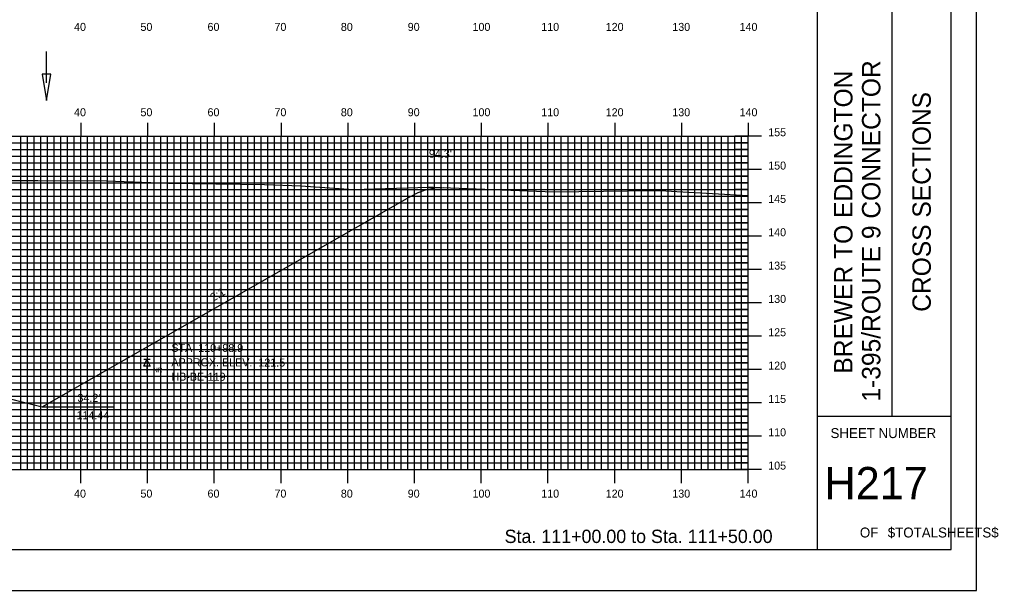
# Model space of a CAD drawing. Extents: x 1769661 to 1770005, y 442591 to 442811.
# Drawn here: x 1769857.8 to 1770004.5, y 442590.5 to 442676.2 of the extents above; entities that cross this region are included whole.
import ezdxf

# ---------------------------------------------------------------- set-up
doc = ezdxf.new("R2010")
doc.units = 0
for name, color, linetype in [('ANNOTATION', 7, 'Continuous'), ('BORDER', 7, 'Continuous'), ('BORING - NO REFUSAL', 7, 'Continuous'), ('D_Drainage_Ditch_Line', 7, 'Continuous'), ('D_Roadway_Centerline', 7, 'Continuous'), ('D_Roadway_SlopeLines', 7, 'Continuous'), ('D_Text_Standard', 7, 'Continuous'), ('H_V ANNOTATION', 7, 'Continuous'), ('MAJOR', 7, 'Continuous'), ('MINOR', 7, 'Continuous'), ('PDRAIN', 7, 'Continuous'), ('PLOT BOUNDARY', 7, 'Continuous'), ('S_Roadway_Centerline', 7, 'Continuous')]:
    doc.layers.add(name, color=color, linetype=linetype)

msp = doc.modelspace()

# ---------------------------------------------------------------- linework, layer by layer
at = {"layer": 'BORDER'}
for p, q in [((1769977.41, 442596.67), (1769977.41, 442806.67)), ((1769988.6, 442616.67), (1769988.6, 442686.67)), ((1769977.41, 442616.67), (1769997.41, 442616.67))]:
    msp.add_line(p, q, dxfattribs=at)
msp.add_lwpolyline([(1769677.41, 442596.67), (1769997.41, 442596.67), (1769997.41, 442806.67), (1769677.41, 442806.67)], close=True, dxfattribs=at)
at = {"layer": 'BORING - NO REFUSAL'}
for p, q in [((1769877.39, 442625.17), (1769876.44, 442625.17)), ((1769876.91, 442624.21), (1769876.91, 442623.15))]:
    msp.add_line(p, q, dxfattribs=at)
msp.add_lwpolyline([(1769876.91, 442625.17), (1769877.39, 442624.21), (1769876.44, 442624.21)], close=True, dxfattribs=at)
at = {"layer": 'D_Drainage_Ditch_Line'}
msp.add_line((1769861.88, 442666.66), (1769861.88, 442671.36), dxfattribs=at)
msp.add_lwpolyline([(1769862.53, 442667.97), (1769861.22, 442667.97), (1769861.88, 442664.03)], close=True, dxfattribs=at)
at = {"layer": 'D_Roadway_Centerline'}
msp.add_lwpolyline([(1769732.37, 442651.1), (1769733.62, 442651.07), (1769734.05, 442650.99), (1769734.87, 442650.84), (1769736.12, 442650.42), (1769737.37, 442649.8), (1769737.37, 442649.8), (1769756.63, 442638.79), (1769792.84, 442618.1), (1769796.84, 442619.1), (1769807.02, 442621.65), (1769815.02, 442621.97), (1769827.02, 442622.21), (1769839.02, 442621.97), (1769847.02, 442621.65), (1769854.85, 442619.69), (1769857.19, 442619.1), (1769861.19, 442618.1), (1769916.31, 442649.6), (1769917.56, 442650.22), (1769918.81, 442650.66), (1769919.51, 442650.8), (1769920.06, 442650.91), (1769921.31, 442650.97)], dxfattribs=at)
at = {"layer": 'D_Roadway_SlopeLines'}
for points in [[(1769861.19, 442618.1), (1769916.31, 442649.6), (1769917.56, 442650.22), (1769918.81, 442650.66), (1769920.06, 442650.91), (1769921.31, 442650.97)], [(1769847.02, 442621.65), (1769861.19, 442618.1)]]:
    msp.add_lwpolyline(points, dxfattribs=at)
at = {"layer": 'MAJOR'}
for p, q in [((1769867.01, 442660.67), (1769867.01, 442658.67)), ((1769877.01, 442660.67), (1769877.01, 442658.67)), ((1769887.01, 442660.67), (1769887.01, 442658.67)), ((1769897.01, 442660.67), (1769897.01, 442658.67)), ((1769907.01, 442660.67), (1769907.01, 442658.67)), ((1769917.01, 442660.67), (1769917.01, 442658.67)), ((1769927.01, 442660.67), (1769927.01, 442658.67)), ((1769937.01, 442660.67), (1769937.01, 442658.67)), ((1769947.01, 442660.67), (1769947.01, 442658.67)), ((1769957.01, 442660.67), (1769957.01, 442658.67)), ((1769967.01, 442660.67), (1769967.01, 442658.67)), ((1769687.01, 442658.67), (1769967.01, 442658.67)), ((1769687.01, 442658.67), (1769967.01, 442658.67)), ((1769867.01, 442608.67), (1769867.01, 442658.67)), ((1769877.01, 442608.67), (1769877.01, 442658.67)), ((1769887.01, 442608.67), (1769887.01, 442658.67)), ((1769897.01, 442608.67), (1769897.01, 442658.67)), ((1769907.01, 442608.67), (1769907.01, 442658.67)), ((1769917.01, 442608.67), (1769917.01, 442658.67)), ((1769927.01, 442608.67), (1769927.01, 442658.67)), ((1769937.01, 442608.67), (1769937.01, 442658.67)), ((1769947.01, 442608.67), (1769947.01, 442658.67)), ((1769957.01, 442608.67), (1769957.01, 442658.67)), ((1769969.02, 442658.67), (1769965.01, 442658.67)), ((1769967.01, 442608.67), (1769967.01, 442658.67)), ((1769967.01, 442608.67), (1769967.01, 442658.67)), ((1769687.01, 442653.67), (1769967.01, 442653.67)), ((1769969.02, 442653.67), (1769965.01, 442653.67)), ((1769687.01, 442648.67), (1769967.01, 442648.67)), ((1769969.02, 442648.67), (1769965.01, 442648.67)), ((1769687.01, 442643.67), (1769967.01, 442643.67)), ((1769969.02, 442643.67), (1769965.01, 442643.67)), ((1769687.01, 442638.67), (1769967.01, 442638.67)), ((1769969.02, 442638.67), (1769965.01, 442638.67)), ((1769687.01, 442633.67), (1769967.01, 442633.67)), ((1769969.02, 442633.67), (1769965.01, 442633.67)), ((1769687.01, 442628.67), (1769967.01, 442628.67)), ((1769969.02, 442628.67), (1769965.01, 442628.67)), ((1769687.01, 442623.67), (1769967.01, 442623.67)), ((1769969.02, 442623.67), (1769965.01, 442623.67)), ((1769687.01, 442618.67), (1769967.01, 442618.67)), ((1769969.02, 442618.67), (1769965.01, 442618.67)), ((1769687.01, 442613.67), (1769967.01, 442613.67)), ((1769969.02, 442613.67), (1769965.01, 442613.67)), ((1769687.01, 442608.67), (1769967.01, 442608.67)), ((1769687.01, 442608.67), (1769967.01, 442608.67)), ((1769867.01, 442606.66), (1769867.01, 442608.67)), ((1769877.01, 442606.66), (1769877.01, 442608.67)), ((1769887.01, 442606.66), (1769887.01, 442608.67)), ((1769897.01, 442606.66), (1769897.01, 442608.67)), ((1769907.01, 442606.66), (1769907.01, 442608.67)), ((1769917.01, 442606.66), (1769917.01, 442608.67)), ((1769927.01, 442606.66), (1769927.01, 442608.67)), ((1769937.01, 442606.66), (1769937.01, 442608.67)), ((1769947.01, 442606.66), (1769947.01, 442608.67)), ((1769957.01, 442606.66), (1769957.01, 442608.67)), ((1769969.02, 442608.67), (1769965.01, 442608.67)), ((1769967.01, 442606.66), (1769967.01, 442608.67))]:
    msp.add_line(p, q, dxfattribs=at)
at = {"layer": 'MINOR'}
for p, q in [((1769858.01, 442608.67), (1769858.01, 442658.67)), ((1769859.01, 442608.67), (1769859.01, 442658.67)), ((1769860.01, 442608.67), (1769860.01, 442658.67)), ((1769861.01, 442608.67), (1769861.01, 442658.67)), ((1769862.01, 442608.67), (1769862.01, 442658.67)), ((1769863.01, 442608.67), (1769863.01, 442658.67)), ((1769864.01, 442608.67), (1769864.01, 442658.67)), ((1769865.01, 442608.67), (1769865.01, 442658.67)), ((1769866.01, 442608.67), (1769866.01, 442658.67)), ((1769868.01, 442608.67), (1769868.01, 442658.67)), ((1769869.01, 442608.67), (1769869.01, 442658.67)), ((1769870.01, 442608.67), (1769870.01, 442658.67)), ((1769871.01, 442608.67), (1769871.01, 442658.67)), ((1769872.01, 442608.67), (1769872.01, 442658.67)), ((1769873.01, 442608.67), (1769873.01, 442658.67)), ((1769874.01, 442608.67), (1769874.01, 442658.67)), ((1769875.01, 442608.67), (1769875.01, 442658.67)), ((1769876.01, 442608.67), (1769876.01, 442658.67)), ((1769878.01, 442608.67), (1769878.01, 442658.67)), ((1769879.01, 442608.67), (1769879.01, 442658.67)), ((1769880.01, 442608.67), (1769880.01, 442658.67)), ((1769881.01, 442608.67), (1769881.01, 442658.67)), ((1769882.01, 442608.67), (1769882.01, 442658.67)), ((1769883.01, 442608.67), (1769883.01, 442658.67)), ((1769884.01, 442608.67), (1769884.01, 442658.67)), ((1769885.01, 442608.67), (1769885.01, 442658.67)), ((1769886.01, 442608.67), (1769886.01, 442658.67)), ((1769888.01, 442608.67), (1769888.01, 442658.67)), ((1769889.01, 442608.67), (1769889.01, 442658.67)), ((1769890.01, 442608.67), (1769890.01, 442658.67)), ((1769891.01, 442608.67), (1769891.01, 442658.67)), ((1769892.01, 442608.67), (1769892.01, 442658.67)), ((1769893.01, 442608.67), (1769893.01, 442658.67)), ((1769894.01, 442608.67), (1769894.01, 442658.67)), ((1769895.01, 442608.67), (1769895.01, 442658.67)), ((1769896.01, 442608.67), (1769896.01, 442658.67)), ((1769898.01, 442608.67), (1769898.01, 442658.67)), ((1769899.01, 442608.67), (1769899.01, 442658.67)), ((1769900.01, 442608.67), (1769900.01, 442658.67)), ((1769901.01, 442608.67), (1769901.01, 442658.67)), ((1769902.01, 442608.67), (1769902.01, 442658.67)), ((1769903.01, 442608.67), (1769903.01, 442658.67)), ((1769904.01, 442608.67), (1769904.01, 442658.67)), ((1769905.01, 442608.67), (1769905.01, 442658.67)), ((1769906.01, 442608.67), (1769906.01, 442658.67)), ((1769908.01, 442608.67), (1769908.01, 442658.67)), ((1769909.01, 442608.67), (1769909.01, 442658.67)), ((1769910.01, 442608.67), (1769910.01, 442658.67)), ((1769911.01, 442608.67), (1769911.01, 442658.67)), ((1769912.01, 442608.67), (1769912.01, 442658.67)), ((1769913.01, 442608.67), (1769913.01, 442658.67)), ((1769914.01, 442608.67), (1769914.01, 442658.67)), ((1769915.01, 442608.67), (1769915.01, 442658.67)), ((1769916.01, 442608.67), (1769916.01, 442658.67)), ((1769918.01, 442608.67), (1769918.01, 442658.67)), ((1769919.01, 442608.67), (1769919.01, 442658.67)), ((1769920.01, 442608.67), (1769920.01, 442658.67)), ((1769921.01, 442608.67), (1769921.01, 442658.67)), ((1769922.01, 442608.67), (1769922.01, 442658.67)), ((1769923.01, 442608.67), (1769923.01, 442658.67)), ((1769924.01, 442608.67), (1769924.01, 442658.67)), ((1769925.01, 442608.67), (1769925.01, 442658.67)), ((1769926.01, 442608.67), (1769926.01, 442658.67)), ((1769928.01, 442608.67), (1769928.01, 442658.67)), ((1769929.01, 442608.67), (1769929.01, 442658.67)), ((1769930.01, 442608.67), (1769930.01, 442658.67)), ((1769931.01, 442608.67), (1769931.01, 442658.67)), ((1769932.01, 442608.67), (1769932.01, 442658.67)), ((1769933.01, 442608.67), (1769933.01, 442658.67)), ((1769934.01, 442608.67), (1769934.01, 442658.67)), ((1769935.01, 442608.67), (1769935.01, 442658.67)), ((1769936.01, 442608.67), (1769936.01, 442658.67)), ((1769938.01, 442608.67), (1769938.01, 442658.67)), ((1769939.01, 442608.67), (1769939.01, 442658.67)), ((1769940.01, 442608.67), (1769940.01, 442658.67)), ((1769941.01, 442608.67), (1769941.01, 442658.67)), ((1769942.01, 442608.67), (1769942.01, 442658.67)), ((1769943.01, 442608.67), (1769943.01, 442658.67)), ((1769944.01, 442608.67), (1769944.01, 442658.67)), ((1769945.01, 442608.67), (1769945.01, 442658.67)), ((1769946.01, 442608.67), (1769946.01, 442658.67)), ((1769948.01, 442608.67), (1769948.01, 442658.67)), ((1769949.01, 442608.67), (1769949.01, 442658.67)), ((1769950.01, 442608.67), (1769950.01, 442658.67)), ((1769951.01, 442608.67), (1769951.01, 442658.67)), ((1769952.01, 442608.67), (1769952.01, 442658.67)), ((1769953.01, 442608.67), (1769953.01, 442658.67)), ((1769954.01, 442608.67), (1769954.01, 442658.67)), ((1769955.01, 442608.67), (1769955.01, 442658.67)), ((1769956.01, 442608.67), (1769956.01, 442658.67)), ((1769958.01, 442608.67), (1769958.01, 442658.67)), ((1769959.01, 442608.67), (1769959.01, 442658.67)), ((1769960.01, 442608.67), (1769960.01, 442658.67)), ((1769961.01, 442608.67), (1769961.01, 442658.67)), ((1769962.01, 442608.67), (1769962.01, 442658.67)), ((1769963.01, 442608.67), (1769963.01, 442658.67)), ((1769964.01, 442608.67), (1769964.01, 442658.67)), ((1769965.01, 442608.67), (1769965.01, 442658.67)), ((1769966.01, 442608.67), (1769966.01, 442658.67)), ((1769687.01, 442657.67), (1769967.01, 442657.67)), ((1769967.01, 442657.67), (1769965.01, 442657.67)), ((1769687.01, 442656.67), (1769967.01, 442656.67)), ((1769687.01, 442655.67), (1769967.01, 442655.67)), ((1769967.01, 442656.67), (1769965.01, 442656.67)), ((1769967.01, 442655.67), (1769965.01, 442655.67)), ((1769687.01, 442654.67), (1769967.01, 442654.67)), ((1769967.01, 442654.67), (1769965.01, 442654.67)), ((1769687.01, 442652.67), (1769967.01, 442652.67)), ((1769967.01, 442652.67), (1769965.01, 442652.67)), ((1769687.01, 442651.67), (1769967.01, 442651.67)), ((1769967.01, 442651.67), (1769965.01, 442651.67)), ((1769687.01, 442650.67), (1769967.01, 442650.67)), ((1769687.01, 442649.67), (1769967.01, 442649.67)), ((1769967.01, 442650.67), (1769965.01, 442650.67)), ((1769967.01, 442649.67), (1769965.01, 442649.67)), ((1769687.01, 442647.67), (1769967.01, 442647.67)), ((1769687.01, 442646.67), (1769967.01, 442646.67)), ((1769967.01, 442647.67), (1769965.01, 442647.67)), ((1769967.01, 442646.67), (1769965.01, 442646.67)), ((1769687.01, 442645.67), (1769967.01, 442645.67)), ((1769967.01, 442645.67), (1769965.01, 442645.67)), ((1769687.01, 442644.67), (1769967.01, 442644.67)), ((1769967.01, 442644.67), (1769965.01, 442644.67)), ((1769687.01, 442642.67), (1769967.01, 442642.67)), ((1769967.01, 442642.67), (1769965.01, 442642.67)), ((1769687.01, 442641.67), (1769967.01, 442641.67)), ((1769687.01, 442640.67), (1769967.01, 442640.67)), ((1769967.01, 442641.67), (1769965.01, 442641.67)), ((1769967.01, 442640.67), (1769965.01, 442640.67)), ((1769687.01, 442639.67), (1769967.01, 442639.67)), ((1769967.01, 442639.67), (1769965.01, 442639.67)), ((1769687.01, 442637.67), (1769967.01, 442637.67)), ((1769967.01, 442637.67), (1769965.01, 442637.67)), ((1769687.01, 442636.67), (1769967.01, 442636.67)), ((1769967.01, 442636.67), (1769965.01, 442636.67)), ((1769687.01, 442635.67), (1769967.01, 442635.67)), ((1769967.01, 442635.67), (1769965.01, 442635.67)), ((1769687.01, 442634.67), (1769967.01, 442634.67)), ((1769967.01, 442634.67), (1769965.01, 442634.67)), ((1769687.01, 442632.67), (1769967.01, 442632.67)), ((1769967.01, 442632.67), (1769965.01, 442632.67)), ((1769687.01, 442631.67), (1769967.01, 442631.67)), ((1769687.01, 442630.67), (1769967.01, 442630.67)), ((1769967.01, 442631.67), (1769965.01, 442631.67)), ((1769967.01, 442630.67), (1769965.01, 442630.67)), ((1769687.01, 442629.67), (1769967.01, 442629.67)), ((1769967.01, 442629.67), (1769965.01, 442629.67)), ((1769687.01, 442627.67), (1769967.01, 442627.67)), ((1769967.01, 442627.67), (1769965.01, 442627.67)), ((1769687.01, 442626.67), (1769967.01, 442626.67)), ((1769967.01, 442626.67), (1769965.01, 442626.67)), ((1769687.01, 442625.67), (1769967.01, 442625.67)), ((1769687.01, 442624.67), (1769967.01, 442624.67)), ((1769967.01, 442625.67), (1769965.01, 442625.67)), ((1769967.01, 442624.67), (1769965.01, 442624.67)), ((1769687.01, 442622.67), (1769967.01, 442622.67)), ((1769687.01, 442621.67), (1769967.01, 442621.67)), ((1769967.01, 442622.67), (1769965.01, 442622.67)), ((1769967.01, 442621.67), (1769965.01, 442621.67)), ((1769687.01, 442620.67), (1769967.01, 442620.67)), ((1769967.01, 442620.67), (1769965.01, 442620.67)), ((1769687.01, 442619.67), (1769967.01, 442619.67)), ((1769967.01, 442619.67), (1769965.01, 442619.67)), ((1769687.01, 442617.67), (1769967.01, 442617.67)), ((1769967.01, 442617.67), (1769965.01, 442617.67)), ((1769687.01, 442616.67), (1769967.01, 442616.67)), ((1769687.01, 442615.67), (1769967.01, 442615.67)), ((1769967.01, 442616.67), (1769965.01, 442616.67)), ((1769967.01, 442615.67), (1769965.01, 442615.67)), ((1769687.01, 442614.67), (1769967.01, 442614.67)), ((1769967.01, 442614.67), (1769965.01, 442614.67)), ((1769687.01, 442612.67), (1769967.01, 442612.67)), ((1769687.01, 442611.67), (1769967.01, 442611.67)), ((1769967.01, 442612.67), (1769965.01, 442612.67)), ((1769967.01, 442611.67), (1769965.01, 442611.67)), ((1769687.01, 442610.67), (1769967.01, 442610.67)), ((1769967.01, 442610.67), (1769965.01, 442610.67)), ((1769687.01, 442609.67), (1769967.01, 442609.67)), ((1769967.01, 442609.67), (1769965.01, 442609.67))]:
    msp.add_line(p, q, dxfattribs=at)
at = {"layer": 'PDRAIN'}
msp.add_line((1769861.19, 442618.1), (1769871.96, 442618.1), dxfattribs=at)
at = {"layer": 'PLOT BOUNDARY'}
msp.add_lwpolyline([(1769661.23, 442590.55), (1770001.23, 442590.55), (1770001.23, 442810.55), (1769661.23, 442810.55)], close=True, dxfattribs=at)
at = {"layer": 'S_Roadway_Centerline'}
msp.add_lwpolyline([(1769855.91, 442652.01), (1769858.8, 442652.03), (1769860.57, 442652.05), (1769870.84, 442651.96), (1769880.12, 442651.65), (1769887.25, 442651.51), (1769894.55, 442651.42), (1769899.99, 442651.22), (1769907.89, 442650.67), (1769919.1, 442651.04), (1769919.82, 442651.03), (1769937.91, 442650.35), (1769949.07, 442650.5), (1769953.88, 442650.53), (1769956.32, 442650.37), (1769967.01, 442649.78)], dxfattribs=at)

# ---------------------------------------------------------------- texts
at = {"layer": 'ANNOTATION'}
msp.add_text('2:1', height=1.2, rotation=29.7454, dxfattribs=at).set_placement((1769886.83, 442633.86))
for s, p in [("34.2'", (1769866.5, 442618.83)), ('114.44', (1769866.36, 442616.23))]:
    msp.add_text(s, height=1.2, dxfattribs=at).set_placement(p)
at = {"layer": 'BORDER'}
for s, p in [('1-395/ROUTE 9 CONNECTOR', (1769986.82, 442618.87)), ('BREWER TO EDDINGTON', (1769982.64, 442623.07)), ('CROSS SECTIONS', (1769994.38, 442632.34))]:
    msp.add_text(s, height=2.7557, rotation=90, dxfattribs=at).set_placement(p)
for s, height, p in [('SHEET NUMBER', 1.4905, (1769979.35, 442613.4)), ('H217', 4.839, (1769978.45, 442604.23)), ('OF', 1.491, (1769983.75, 442598.49)), ('$TOTALSHEETS$', 1.4905, (1769987.93, 442598.49))]:
    msp.add_text(s, height=height, dxfattribs=at).set_placement(p)
at = {"layer": 'BORING - NO REFUSAL'}
for s, p in [('STA. 110+98.9', (1769880.58, 442626.34)), ('APPROX. ELEV.  121.5', (1769880.58, 442624.18)), ('HB-BE-119', (1769880.57, 442622.02))]:
    msp.add_text(s, height=1.2, rotation=359.8142, dxfattribs=at).set_placement(p)
msp.add_text('NR', height=0.7, dxfattribs=at).set_placement((1769877.85, 442623.25))
at = {"layer": 'D_Text_Standard'}
msp.add_text("94.3'", height=1.2, dxfattribs=at).set_placement((1769919.17, 442655.45))
at = {"layer": 'H_V ANNOTATION'}
for s, height, p in [('40', 1.2, (1769865.99, 442674.47)), ('50', 1.2, (1769875.94, 442674.47)), ('60', 1.2, (1769885.99, 442674.47)), ('70', 1.2, (1769896.02, 442674.47)), ('80', 1.2, (1769905.97, 442674.47)), ('90', 1.2, (1769915.99, 442674.47)), ('100', 1.2, (1769925.7, 442674.47)), ('110', 1.2, (1769936, 442674.47)), ('120', 1.2, (1769945.66, 442674.47)), ('130', 1.2, (1769955.64, 442674.47)), ('140', 1.2, (1769965.72, 442674.47)), ('40', 1.2, (1769865.99, 442661.67)), ('50', 1.2, (1769875.94, 442661.67)), ('60', 1.2, (1769885.99, 442661.67)), ('70', 1.2, (1769896.02, 442661.67)), ('80', 1.2, (1769905.97, 442661.67)), ('90', 1.2, (1769915.99, 442661.67)), ('100', 1.2, (1769925.7, 442661.67)), ('110', 1.2, (1769936, 442661.67)), ('120', 1.2, (1769945.66, 442661.67)), ('130', 1.2, (1769955.64, 442661.67)), ('140', 1.2, (1769965.72, 442661.67)), ('155', 1.2, (1769970.01, 442658.67)), ('150', 1.2, (1769970.01, 442653.67)), ('145', 1.2, (1769970.01, 442648.67)), ('140', 1.2, (1769970.01, 442643.67)), ('135', 1.2, (1769970.01, 442638.67)), ('130', 1.2, (1769970.01, 442633.67)), ('125', 1.2, (1769970.01, 442628.67)), ('120', 1.2, (1769970.01, 442623.67)), ('115', 1.2, (1769970.01, 442618.67)), ('110', 1.2, (1769970.01, 442613.67)), ('105', 1.2, (1769970.01, 442608.67)), ('40', 1.2, (1769865.99, 442604.47)), ('50', 1.2, (1769875.94, 442604.47)), ('60', 1.2, (1769885.99, 442604.47)), ('70', 1.2, (1769896.02, 442604.47)), ('80', 1.2, (1769905.97, 442604.47)), ('90', 1.2, (1769915.99, 442604.47)), ('100', 1.2, (1769925.7, 442604.47)), ('110', 1.2, (1769936, 442604.47)), ('120', 1.2, (1769945.66, 442604.47)), ('130', 1.2, (1769955.64, 442604.47)), ('140', 1.2, (1769965.72, 442604.47)), ('Sta. 111+00.00 to Sta. 111+50.00', 2.0004, (1769930.51, 442597.66))]:
    msp.add_text(s, height=height, dxfattribs=at).set_placement(p)

doc.saveas('drawing.dxf')
